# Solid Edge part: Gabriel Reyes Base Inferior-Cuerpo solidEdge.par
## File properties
Author: owner
Template: iso metric part.par
Last saved by: owner
Revision: 1
Application: Solid Edge
Precisión: 0.990
Username: owner
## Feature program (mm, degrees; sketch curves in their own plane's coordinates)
body "unnamed Body 1"
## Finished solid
Body 1: solid body, 180 faces, 513 edges, 338 vertices.
  Faces by surface: plane 148, swept 18, cylinder 14
  Edges by curve: line 438, spline 38, curve on surface 21, circle 16
Bounding box of the edges (mm; curved faces can reach further): 107.000 x 87.700 x 20.800, from (-53.5, -43.85, -5) to (53.5, 43.85, 15.8).
Cylindrical faces by radius (mm): R0.8283 x1, R0.8313 x1, R1.2 x2, R1.5 x4, R2.4 x2, R2.4748 x1, R2.475 x1, R2.5026 x1, R2.5028 x1
Planar faces by outward normal: +x 25, +y 24, +z 25, -x 25, -y 29, -z 9, oblique 11
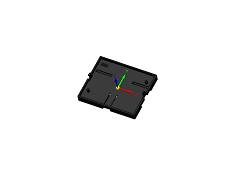
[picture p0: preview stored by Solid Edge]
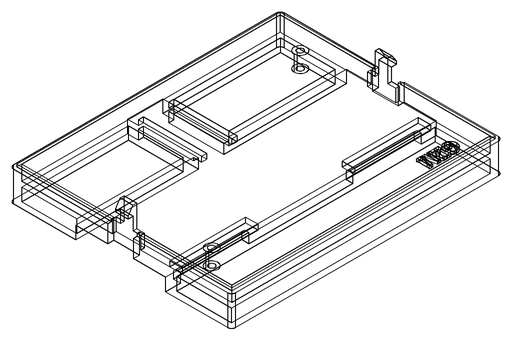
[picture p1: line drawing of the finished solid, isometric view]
